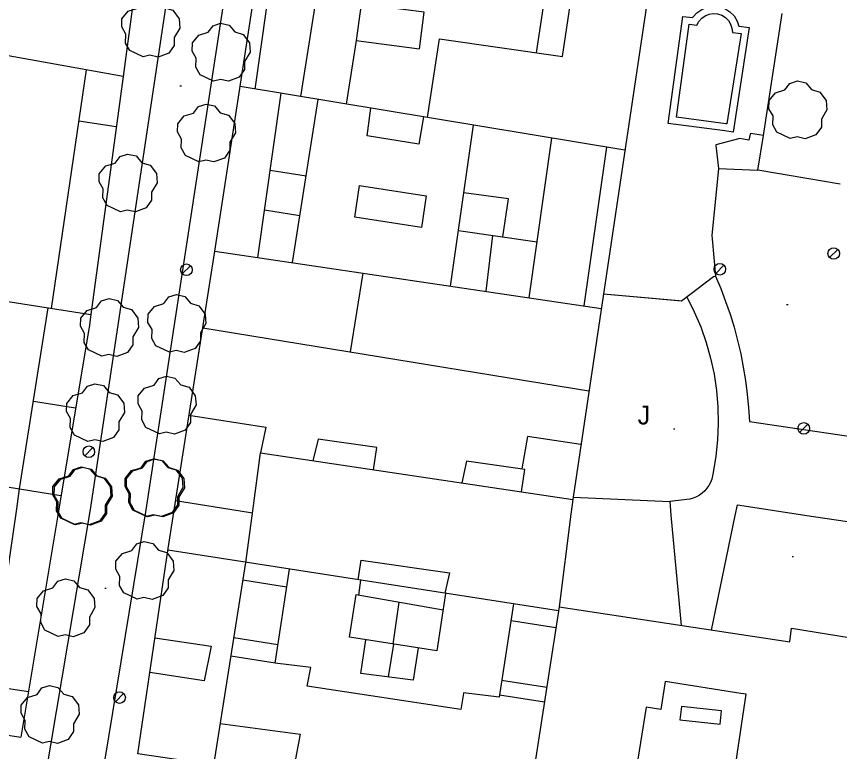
# Model space of a CAD drawing. Extents: x 431390 to 432653, y 4586754 to 4589600.
# Drawn here: x 431891.7 to 431948.5, y 4587166.9 to 4587217.7 of the extents above; entities that cross this region are included whole.
import ezdxf

# ---------------------------------------------------------------- set-up
doc = ezdxf.new("R2010")
doc.units = 0
for name, color, linetype in [('COM_17LS_LN', 7, 'Continuous'), ('CON_01_LN', 7, 'Continuous'), ('CON_01FI_LN', 7, 'Continuous'), ('CON_03_LN', 7, 'Continuous'), ('CON_04_LN', 7, 'Continuous'), ('CON_07_LN', 7, 'Continuous'), ('CON_16_LN', 7, 'Continuous'), ('CON_29_LN', 7, 'Continuous'), ('ENE_06_PT', 7, 'Continuous'), ('ENE_08_LN', 7, 'Continuous'), ('HID_11EX_LN', 7, 'Continuous'), ('HID_11IN_LN', 7, 'Continuous'), ('ORO_03_PT', 7, 'Continuous'), ('TOP_15JA_TX', 7, 'Continuous'), ('VEG_03_PT', 7, 'Continuous'), ('VEG_04_LN', 7, 'Continuous'), ('VEG_06_LN', 7, 'Continuous')]:
    doc.layers.add(name, color=color, linetype=linetype)

msp = doc.modelspace()

# ---------------------------------------------------------------- linework, layer by layer
at = {"layer": 'COM_17LS_LN'}
for points in [[(431987.522, 4587199.068), (432038.841, 4587190.205), (432037.603, 4587182.271), (432031.666, 4587144.248), (431980.566, 4587151.892), (431980.618, 4587152.238), (431953.282, 4587155.989), (431897.468, 4587164.433), (431900.621, 4587183.589), (431910.828, 4587250.379), (431908.915, 4587250.666), (431906.855, 4587250.975), (431896.747, 4587183.627), (431893.612, 4587165.02)], [(431939.909, 4587199.737), (431940.273, 4587198.868), (431940.608, 4587197.988), (431940.913, 4587197.098), (431941.188, 4587196.197), (431941.432, 4587195.288), (431941.646, 4587194.371), (431941.828, 4587193.447), (431941.979, 4587192.518), (431942.098, 4587191.584), (431942.186, 4587190.646), (431942.243, 4587189.707), (431952.211, 4587188.212)]]:
    msp.add_lwpolyline(points, dxfattribs=at)
at = {"layer": 'CON_01_LN'}
for points in [[(431905.047, 4587251.483), (431899.791, 4587219.218), (431899.022, 4587213.51)], [(431976.55, 4587170), (431974.598, 4587155.675), (431958.73, 4587157.956), (431942.881, 4587160.322), (431926.807, 4587162.814), (431900.035, 4587166.752), (431902.124, 4587180.926), (431902.539, 4587183.571), (431905.349, 4587201.465), (431909.625, 4587229.31), (431912.812, 4587250.081), (431939.244, 4587245.294), (431970.672, 4587239.706), (431986.669, 4587236.944), (431980.405, 4587194.435), (431980.391, 4587194.245), (431978.82, 4587183.839)], [(431899.022, 4587213.51), (431896.807, 4587197.074)], [(431896.807, 4587197.074), (431896.688, 4587196.192), (431896.651, 4587196.1), (431894.58, 4587183.648), (431891.961, 4587167.894)], [(431847.142, 4587174.799), (431891.961, 4587167.894)]]:
    msp.add_lwpolyline(points, dxfattribs=at)
at = {"layer": 'CON_01FI_LN'}
msp.add_lwpolyline([(431935.309, 4587219.497), (431930.075, 4587184.476), (431929.928, 4587183.307), (431929.122, 4587176.908), (431945.032, 4587174.478), (431945.162, 4587175.438), (431949.987, 4587174.645), (431950.029, 4587174.905), (431955.325, 4587174.095), (431956.508, 4587179.752), (431956.552, 4587179.742), (431961.716, 4587178.998), (431962.494, 4587182.994), (431962.5, 4587183.025), (431962.668, 4587182.992), (431966.987, 4587182.151), (431965.51, 4587169.018), (431970.215, 4587168.295), (431970.527, 4587170.834), (431976.55, 4587170)], dxfattribs=at)
at = {"layer": 'CON_03_LN'}
for points in [[(431899.022, 4587213.51), (431888.261, 4587215.434), (431888.155, 4587214.982), (431886.975, 4587215.174)], [(431933.656, 4587208.434), (431907.092, 4587212.818)], [(431905.349, 4587201.465), (431932.021, 4587197.5)], [(431876.39, 4587200.272), (431896.807, 4587197.074)], [(431904.517, 4587196.168), (431931.171, 4587191.809)], [(431874.496, 4587187.875), (431891.882, 4587185.044), (431894.735, 4587184.58)], [(431905.278, 4587165.981), (431907.486, 4587179.973), (431907.968, 4587183.519), (431908.512, 4587187.523), (431930.055, 4587184.319)], [(431929.077, 4587176.616), (431902.107, 4587180.81)], [(431929.122, 4587176.908), (431926.925, 4587162.796)]]:
    msp.add_lwpolyline(points, dxfattribs=at)
at = {"layer": 'CON_04_LN'}
for points in [[(431908.137, 4587212.646), (431909.758, 4587224.029)], [(431928.386, 4587220.813), (431927.53, 4587215.152)], [(431920.025, 4587210.684), (431920.859, 4587216.115), (431929.341, 4587214.891), (431930.183, 4587220.471)], [(431915.449, 4587218.515), (431915.119, 4587215.988), (431919.476, 4587215.418), (431919.806, 4587217.946), (431915.449, 4587218.515)], [(431915.119, 4587215.988), (431914.429, 4587211.607)], [(431894.083, 4587197.501), (431896.499, 4587213.961)], [(431908.33, 4587201.022), (431909.924, 4587212.351)], [(431910.717, 4587200.667), (431912.495, 4587211.926)], [(431919.746, 4587210.73), (431919.434, 4587208.833), (431915.873, 4587209.409), (431916.128, 4587211.327)], [(431898.554, 4587210.04), (431895.979, 4587210.417)], [(431921.623, 4587199.046), (431923.205, 4587210.159)], [(431927.044, 4587198.24), (431928.619, 4587209.265)], [(431932.392, 4587208.643), (431930.814, 4587197.679)], [(431909.179, 4587207.054), (431911.664, 4587206.661)], [(431915.346, 4587205.978), (431919.945, 4587205.264), (431919.608, 4587203.094), (431915.009, 4587203.807), (431915.346, 4587205.978)], [(431925.229, 4587202.434), (431925.613, 4587205.056), (431922.54, 4587205.488)], [(431908.792, 4587204.306), (431911.231, 4587203.92)], [(431922.168, 4587202.872), (431927.595, 4587202.096)], [(431924.521, 4587202.536), (431924.046, 4587198.686)], [(431870.99, 4587173.556), (431889.81, 4587170.806), (431891.683, 4587183.675), (431891.882, 4587185.044), (431893.85, 4587197.537)], [(431895.74, 4587190.622), (431892.833, 4587191.079)], [(431903.569, 4587190.128), (431908.868, 4587189.296), (431908.512, 4587187.523)], [(431916.315, 4587186.362), (431916.544, 4587187.9), (431912.476, 4587188.48), (431912.107, 4587186.988)], [(431930.619, 4587188.116), (431926.943, 4587188.666), (431926.536, 4587186.422)], [(431926.518, 4587184.845), (431926.749, 4587186.392), (431922.712, 4587186.969), (431922.405, 4587185.457)], [(431907.948, 4587183.375), (431906.971, 4587183.528), (431902.639, 4587184.208)], [(431915.247, 4587178.767), (431915.457, 4587180.114), (431921.543, 4587179.252), (431921.238, 4587177.835)], [(431925.976, 4587177.098), (431924.968, 4587170.668), (431922.523, 4587170.956), (431922.512, 4587170.916), (431922.325, 4587169.809), (431911.734, 4587171.427), (431911.975, 4587172.708), (431909.507, 4587173.015), (431910.501, 4587179.505)], [(431910.31, 4587178.261), (431907.291, 4587178.737)], [(431915.284, 4587177.718), (431915.442, 4587178.736)], [(431921.282, 4587177.828), (431920.666, 4587173.865), (431914.654, 4587174.799), (431915.112, 4587177.748), (431921.107, 4587176.702)], [(431925.796, 4587175.95), (431928.898, 4587175.467)], [(431901.215, 4587174.757), (431905.102, 4587174.185), (431904.626, 4587171.798), (431900.864, 4587172.374)], [(431909.701, 4587174.281), (431906.663, 4587174.76)], [(431919.384, 4587174.064), (431919.041, 4587171.85), (431915.434, 4587172.3), (431915.787, 4587174.623)], [(431909.507, 4587173.015), (431906.464, 4587173.495)], [(431925.15, 4587171.83), (431928.256, 4587171.346)], [(431892.484, 4587171.041), (431889.899, 4587171.417)], [(431941.645, 4587170.915), (431936.434, 4587171.738), (431936.129, 4587169.812), (431935.117, 4587169.972), (431934.346, 4587165.098), (431941.003, 4587164.086), (431942.033, 4587170.867), (431941.645, 4587170.915)], [(431924.993, 4587170.825), (431928.1, 4587170.341)], [(431905.73, 4587168.845), (431911.244, 4587168.106), (431910.701, 4587165.183)]]:
    msp.add_lwpolyline(points, dxfattribs=at)
at = {"layer": 'CON_07_LN'}
msp.add_lwpolyline([(431943.209, 4587209.445), (431942.316, 4587209.581), (431942.307, 4587209.533), (431942.209, 4587209.111), (431941.581, 4587209.227), (431939.92, 4587208.79), (431939.921, 4587208.755), (431940.115, 4587207.157), (431942.837, 4587207.041), (431943.209, 4587209.445)], dxfattribs=at)
at = {"layer": 'CON_16_LN'}
for points in [[(431943.209, 4587209.445), (431944.515, 4587217.858)], [(431940.115, 4587207.157), (431939.662, 4587202.537), (431939.67, 4587202.301), (431939.909, 4587199.737), (431939.777, 4587199.671), (431937.552, 4587198.001), (431937.388, 4587198.033), (431932.169, 4587198.485)], [(431948.522, 4587206.082), (431942.837, 4587207.041)], [(431930.075, 4587184.476), (431936.751, 4587184.171), (431936.836, 4587183.241), (431937.531, 4587175.624)], [(431939.635, 4587175.302), (431941.264, 4587183.198), (431941.416, 4587183.937), (431946.66, 4587183.146), (431951.366, 4587182.437)]]:
    msp.add_lwpolyline(points, dxfattribs=at)
at = {"layer": 'CON_29_LN'}
for points in [[(431913.058, 4587223.496), (431911.266, 4587212.129)], [(431915.58, 4587199.944), (431914.69, 4587194.504)], [(431918.052, 4587177.235), (431917.631, 4587174.336)], [(431917.686, 4587174.328), (431917.308, 4587172.066)]]:
    msp.add_lwpolyline(points, dxfattribs=at)
at = {"layer": 'ENE_06_PT'}
for p, q in [((431948.351, 4587201.574), (431947.785, 4587201.008)), ((431903.677, 4587200.452), (431903.111, 4587199.886)), ((431940.488, 4587200.489), (431939.922, 4587199.923)), ((431946.281, 4587189.502), (431945.715, 4587188.936)), ((431896.94, 4587187.891), (431896.374, 4587187.325)), ((431899.062, 4587170.916), (431898.496, 4587170.35))]:
    msp.add_line(p, q, dxfattribs=at)
for centre in [(431948.068, 4587201.291), (431903.394, 4587200.169), (431940.205, 4587200.206), (431945.998, 4587189.219), (431896.657, 4587187.608), (431898.779, 4587170.633)]:
    msp.add_circle(centre, 0.4, dxfattribs=at)
at = {"layer": 'ENE_08_LN'}
msp.add_lwpolyline([(431937.448, 4587169.105), (431940.224, 4587168.794), (431940.327, 4587169.72), (431937.551, 4587170.03), (431937.448, 4587169.105)], dxfattribs=at)
at = {"layer": 'HID_11EX_LN'}
msp.add_lwpolyline([(431938.338, 4587217.587), (431938.344, 4587217.599), (431938.616, 4587217.909), (431938.953, 4587218.148), (431939.335, 4587218.301), (431939.742, 4587218.364), (431940.155, 4587218.329), (431940.546, 4587218.2), (431940.897, 4587217.984), (431941.189, 4587217.694), (431941.407, 4587217.342), (431941.521, 4587216.993), (431942.24, 4587216.892), (431941.116, 4587209.668), (431940.557, 4587209.752), (431936.65, 4587210.27), (431937.66, 4587217.662), (431938.338, 4587217.587)], dxfattribs=at)
at = {"layer": 'HID_11IN_LN'}
msp.add_lwpolyline([(431938.62, 4587217.054), (431938.758, 4587217.314), (431938.953, 4587217.536), (431939.194, 4587217.707), (431939.468, 4587217.817), (431939.76, 4587217.862), (431940.055, 4587217.837), (431940.335, 4587217.745), (431940.587, 4587217.59), (431940.796, 4587217.382), (431940.952, 4587217.13), (431941.045, 4587216.85), (431941.071, 4587216.556), (431941.67, 4587216.47), (431940.7, 4587210.236), (431940.627, 4587210.247), (431937.213, 4587210.699), (431938.089, 4587217.113), (431938.62, 4587217.054)], dxfattribs=at)
at = {"layer": 'ORO_03_PT'}
for p, q in [((431902.944, 4587212.863), (431903.044, 4587212.863)), ((431944.818, 4587197.784), (431944.918, 4587197.784)), ((431937.009, 4587189.184), (431937.109, 4587189.184)), ((431945.189, 4587180.382), (431945.289, 4587180.382)), ((431897.765, 4587178.19), (431897.865, 4587178.19))]:
    msp.add_line(p, q, dxfattribs=at)
at = {"layer": 'VEG_03_PT'}
for points in [[(431900.409, 4587214.868), (431899.482, 4587215.303), (431899.194, 4587215.824), (431899.217, 4587216.438), (431898.935, 4587216.93), (431898.943, 4587217.493), (431899.384, 4587218.028), (431900.037, 4587218.232), (431900.372, 4587218.683), (431900.898, 4587218.853), (431901.478, 4587218.72), (431901.878, 4587218.254), (431902.452, 4587218.084), (431902.886, 4587217.501), (431902.935, 4587216.859), (431902.552, 4587216.212), (431902.552, 4587215.662), (431902.18, 4587215.128), (431901.441, 4587214.853), (431900.876, 4587214.981), (431900.409, 4587214.868)], [(431905.268, 4587213.2), (431904.341, 4587213.635), (431904.053, 4587214.156), (431904.076, 4587214.77), (431903.794, 4587215.262), (431903.802, 4587215.825), (431904.243, 4587216.36), (431904.896, 4587216.564), (431905.231, 4587217.015), (431905.757, 4587217.185), (431906.337, 4587217.052), (431906.737, 4587216.586), (431907.311, 4587216.416), (431907.745, 4587215.833), (431907.794, 4587215.191), (431907.411, 4587214.544), (431907.411, 4587213.994), (431907.039, 4587213.46), (431906.3, 4587213.185), (431905.735, 4587213.313), (431905.268, 4587213.2)], [(431945.072, 4587209.224), (431944.145, 4587209.659), (431943.857, 4587210.18), (431943.88, 4587210.794), (431943.598, 4587211.286), (431943.606, 4587211.849), (431944.047, 4587212.384), (431944.7, 4587212.588), (431945.035, 4587213.039), (431945.561, 4587213.209), (431946.141, 4587213.076), (431946.541, 4587212.61), (431947.115, 4587212.44), (431947.549, 4587211.857), (431947.598, 4587211.215), (431947.215, 4587210.568), (431947.215, 4587210.018), (431946.843, 4587209.484), (431946.104, 4587209.209), (431945.539, 4587209.337), (431945.072, 4587209.224)], [(431904.257, 4587207.625), (431903.33, 4587208.06), (431903.042, 4587208.581), (431903.065, 4587209.195), (431902.783, 4587209.687), (431902.791, 4587210.25), (431903.232, 4587210.785), (431903.885, 4587210.989), (431904.22, 4587211.44), (431904.746, 4587211.61), (431905.326, 4587211.477), (431905.726, 4587211.011), (431906.3, 4587210.841), (431906.734, 4587210.258), (431906.783, 4587209.616), (431906.4, 4587208.969), (431906.4, 4587208.419), (431906.028, 4587207.885), (431905.289, 4587207.61), (431904.724, 4587207.738), (431904.257, 4587207.625)], [(431898.847, 4587204.176), (431897.92, 4587204.611), (431897.632, 4587205.132), (431897.655, 4587205.746), (431897.373, 4587206.238), (431897.381, 4587206.801), (431897.822, 4587207.336), (431898.475, 4587207.54), (431898.81, 4587207.991), (431899.336, 4587208.161), (431899.916, 4587208.028), (431900.316, 4587207.562), (431900.89, 4587207.392), (431901.324, 4587206.809), (431901.373, 4587206.167), (431900.99, 4587205.52), (431900.99, 4587204.97), (431900.618, 4587204.436), (431899.879, 4587204.161), (431899.314, 4587204.289), (431898.847, 4587204.176)], [(431897.563, 4587194.204), (431896.636, 4587194.639), (431896.348, 4587195.16), (431896.371, 4587195.774), (431896.089, 4587196.266), (431896.097, 4587196.829), (431896.538, 4587197.364), (431897.191, 4587197.568), (431897.526, 4587198.019), (431898.052, 4587198.189), (431898.632, 4587198.056), (431899.032, 4587197.59), (431899.606, 4587197.42), (431900.04, 4587196.837), (431900.089, 4587196.195), (431899.706, 4587195.548), (431899.706, 4587194.998), (431899.334, 4587194.464), (431898.595, 4587194.189), (431898.03, 4587194.317), (431897.563, 4587194.204)], [(431902.215, 4587194.476), (431901.288, 4587194.911), (431901, 4587195.432), (431901.023, 4587196.046), (431900.741, 4587196.538), (431900.749, 4587197.101), (431901.19, 4587197.636), (431901.843, 4587197.84), (431902.178, 4587198.291), (431902.704, 4587198.461), (431903.284, 4587198.328), (431903.684, 4587197.862), (431904.258, 4587197.692), (431904.692, 4587197.109), (431904.741, 4587196.467), (431904.358, 4587195.82), (431904.358, 4587195.27), (431903.986, 4587194.736), (431903.247, 4587194.461), (431902.682, 4587194.589), (431902.215, 4587194.476)], [(431901.53, 4587188.844), (431900.603, 4587189.279), (431900.315, 4587189.8), (431900.338, 4587190.414), (431900.056, 4587190.906), (431900.064, 4587191.469), (431900.505, 4587192.004), (431901.158, 4587192.208), (431901.493, 4587192.659), (431902.019, 4587192.829), (431902.599, 4587192.696), (431902.999, 4587192.23), (431903.573, 4587192.06), (431904.007, 4587191.477), (431904.056, 4587190.835), (431903.673, 4587190.188), (431903.673, 4587189.638), (431903.301, 4587189.104), (431902.562, 4587188.829), (431901.997, 4587188.957), (431901.53, 4587188.844)], [(431896.595, 4587188.322), (431895.668, 4587188.757), (431895.38, 4587189.278), (431895.403, 4587189.892), (431895.121, 4587190.384), (431895.129, 4587190.947), (431895.57, 4587191.482), (431896.223, 4587191.686), (431896.558, 4587192.137), (431897.084, 4587192.307), (431897.664, 4587192.174), (431898.064, 4587191.708), (431898.638, 4587191.538), (431899.072, 4587190.955), (431899.121, 4587190.313), (431898.738, 4587189.666), (431898.738, 4587189.116), (431898.366, 4587188.582), (431897.627, 4587188.307), (431897.062, 4587188.435), (431896.595, 4587188.322)], [(431900.631, 4587183.143), (431899.704, 4587183.578), (431899.416, 4587184.099), (431899.439, 4587184.713), (431899.157, 4587185.205), (431899.165, 4587185.768), (431899.606, 4587186.303), (431900.259, 4587186.507), (431900.594, 4587186.958), (431901.12, 4587187.128), (431901.7, 4587186.995), (431902.1, 4587186.529), (431902.674, 4587186.359), (431903.108, 4587185.776), (431903.157, 4587185.134), (431902.774, 4587184.487), (431902.774, 4587183.937), (431902.402, 4587183.403), (431901.663, 4587183.128), (431901.098, 4587183.256), (431900.631, 4587183.143)], [(431900.73, 4587183.126), (431899.803, 4587183.561), (431899.515, 4587184.082), (431899.538, 4587184.696), (431899.256, 4587185.188), (431899.264, 4587185.751), (431899.705, 4587186.286), (431900.358, 4587186.49), (431900.693, 4587186.941), (431901.219, 4587187.111), (431901.799, 4587186.978), (431902.199, 4587186.512), (431902.773, 4587186.342), (431903.207, 4587185.759), (431903.256, 4587185.117), (431902.873, 4587184.47), (431902.873, 4587183.92), (431902.501, 4587183.386), (431901.762, 4587183.111), (431901.197, 4587183.239), (431900.73, 4587183.126)], [(431895.646, 4587182.577), (431894.719, 4587183.012), (431894.431, 4587183.533), (431894.454, 4587184.147), (431894.172, 4587184.639), (431894.18, 4587185.202), (431894.621, 4587185.737), (431895.274, 4587185.941), (431895.609, 4587186.392), (431896.135, 4587186.562), (431896.715, 4587186.429), (431897.115, 4587185.963), (431897.689, 4587185.793), (431898.123, 4587185.21), (431898.172, 4587184.568), (431897.789, 4587183.921), (431897.789, 4587183.371), (431897.417, 4587182.837), (431896.678, 4587182.562), (431896.113, 4587182.69), (431895.646, 4587182.577)], [(431895.745, 4587182.56), (431894.818, 4587182.995), (431894.53, 4587183.516), (431894.553, 4587184.13), (431894.271, 4587184.622), (431894.279, 4587185.185), (431894.72, 4587185.72), (431895.373, 4587185.924), (431895.708, 4587186.375), (431896.234, 4587186.545), (431896.814, 4587186.412), (431897.214, 4587185.946), (431897.788, 4587185.776), (431898.222, 4587185.193), (431898.271, 4587184.551), (431897.888, 4587183.904), (431897.888, 4587183.354), (431897.516, 4587182.82), (431896.777, 4587182.545), (431896.212, 4587182.673), (431895.745, 4587182.56)], [(431899.998, 4587177.43), (431899.071, 4587177.865), (431898.783, 4587178.386), (431898.806, 4587179), (431898.524, 4587179.492), (431898.532, 4587180.055), (431898.973, 4587180.59), (431899.626, 4587180.794), (431899.961, 4587181.245), (431900.487, 4587181.415), (431901.067, 4587181.282), (431901.467, 4587180.816), (431902.041, 4587180.646), (431902.475, 4587180.063), (431902.524, 4587179.421), (431902.141, 4587178.774), (431902.141, 4587178.224), (431901.769, 4587177.69), (431901.03, 4587177.415), (431900.465, 4587177.543), (431899.998, 4587177.43)], [(431894.552, 4587174.855), (431893.625, 4587175.29), (431893.337, 4587175.811), (431893.36, 4587176.425), (431893.078, 4587176.917), (431893.086, 4587177.48), (431893.527, 4587178.015), (431894.18, 4587178.219), (431894.515, 4587178.67), (431895.041, 4587178.84), (431895.621, 4587178.707), (431896.021, 4587178.241), (431896.595, 4587178.071), (431897.029, 4587177.488), (431897.078, 4587176.846), (431896.695, 4587176.199), (431896.695, 4587175.649), (431896.323, 4587175.115), (431895.584, 4587174.84), (431895.019, 4587174.968), (431894.552, 4587174.855)], [(431893.458, 4587167.493), (431892.531, 4587167.928), (431892.243, 4587168.449), (431892.266, 4587169.063), (431891.984, 4587169.555), (431891.992, 4587170.118), (431892.433, 4587170.653), (431893.086, 4587170.857), (431893.421, 4587171.308), (431893.947, 4587171.478), (431894.527, 4587171.345), (431894.927, 4587170.879), (431895.501, 4587170.709), (431895.935, 4587170.126), (431895.984, 4587169.484), (431895.601, 4587168.837), (431895.601, 4587168.287), (431895.229, 4587167.753), (431894.49, 4587167.478), (431893.925, 4587167.606), (431893.458, 4587167.493)]]:
    msp.add_lwpolyline(points, dxfattribs=at)
at = {"layer": 'VEG_04_LN'}
msp.add_lwpolyline([(431937.552, 4587198.001), (431932.169, 4587198.485)], dxfattribs=at)
at = {"layer": 'VEG_06_LN'}
msp.add_lwpolyline([(431937.938, 4587198.291), (431938.444, 4587197.274), (431938.886, 4587196.228), (431939.262, 4587195.156), (431939.569, 4587194.063), (431939.806, 4587192.952), (431939.973, 4587191.829), (431940.069, 4587190.697), (431940.094, 4587189.562), (431940.048, 4587188.427), (431939.929, 4587187.297), (431939.741, 4587186.178), (431939.707, 4587185.943), (431939.647, 4587185.714), (431939.561, 4587185.493), (431939.45, 4587185.283), (431939.317, 4587185.087), (431939.162, 4587184.908), (431938.988, 4587184.747), (431938.796, 4587184.608), (431938.59, 4587184.491), (431938.372, 4587184.398), (431938.145, 4587184.331), (431936.751, 4587184.171)], dxfattribs=at)

# ---------------------------------------------------------------- texts
at = {"layer": 'TOP_15JA_TX'}
msp.add_text('J', height=1.3, dxfattribs=at).set_placement((431934.535, 4587189.491))

doc.saveas('drawing.dxf')
